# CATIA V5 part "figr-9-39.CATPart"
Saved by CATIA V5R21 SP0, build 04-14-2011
Part number: Part1
Bounding box of the stored display mesh (mm): x -40 to 40, y -20 to 191.034, z 0 to 131.022
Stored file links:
  D:\CATIA V5R21 E-RESOURCES\CATIA-V5R21\catia-v5r21-prt\c09-catia-v5r20-prt\c09-catia-v5r21-figr-9-39.CATPart
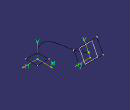
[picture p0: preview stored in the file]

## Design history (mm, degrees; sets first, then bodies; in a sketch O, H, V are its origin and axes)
Set1
  Plane1: type Normal, Curve Sketch2, RefPoint vertex of Sketch2
Body1 (main body)
  Sketch1 on xy-plane, origin (0, 0, 0), H (1, 0, 0), V (0, 1, 0)
    line L1 (20, 20) -> (20, -20)
    line L2 (20, -20) -> (-20, -20)
    line L3 (-20, -20) -> (-20, 20)
    line L4 (-20, 20) -> (20, 20)
    vertical: L1 V, L3 V
    horizontal: L2 H, L4 H
    equidistance: L1 L3 O, L2 L4 O
  Sketch2 on yz-plane, origin (0, 0, 0), H (0, 1, 0), V (0, 0, 1)
    spline S1 through (0, 0) (20, 60) (60, 80) (120, 90) (180, 110)
    point P1 (0, 0)
    coincidence: P1 O
  Sketch3 on Plane1, origin (0, 186.3865, 97.8327), H (1, 0, 0), V (0, -0.4648, 0.8854)
    point P1 (0, 13.7415)
    line L1 (40, 37.4831) -> (40, -10)
    line L2 (40, -10) -> (-40, -10)
    line L3 (-40, -10) -> (-40, 37.4831)
    line L4 (-40, 37.4831) -> (40, 37.4831)
    reference projected point E1 (0, 13.7415) from vertex of Sketch2
    coincidence: P1 V, P1 E1
    vertical: L1 V, L3 V
    horizontal: L2 H, L4 H
    equidistance: L1 L3 P1, L2 L4 P1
